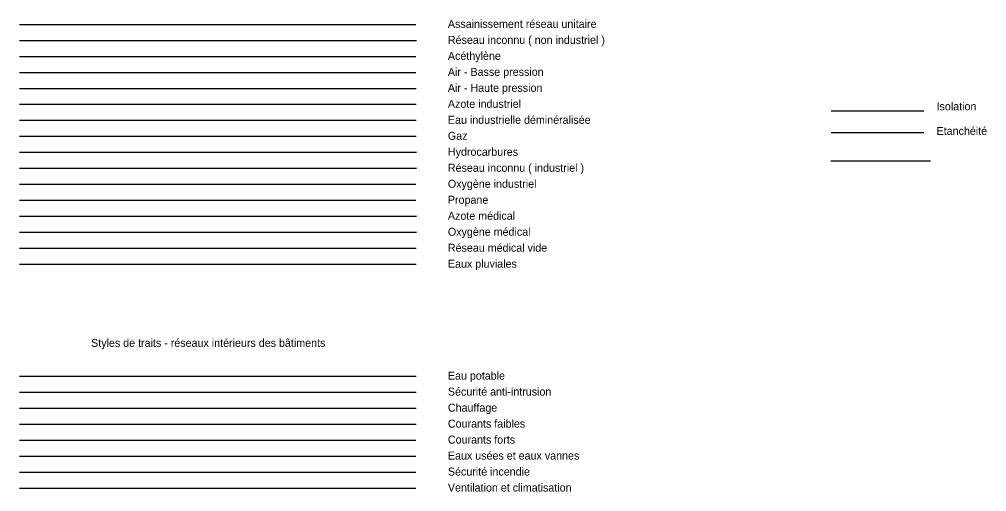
# Model space of a CAD drawing. Extents: x 3494.1 to 3554.6, y -18944.5 to -18883.7.
# Drawn here: x 3494.1 to 3554.6, y -18944.5 to -18915 of the extents above; entities that cross this region are included whole.
import ezdxf

# ---------------------------------------------------------------- set-up
doc = ezdxf.new("R2010")
doc.units = 0
for name, color, linetype in [('GO_COUVERTURE', 7, 'Continuous'), ('R_ES_UNITAIRE_CANALISATION_CL_C', 7, 'Continuous'), ('R_INCONNU_CANALISATION_CL_C', 7, 'Continuous'), ('R_IND_ACETYLENE_CANALISATION_CL_C', 7, 'Continuous'), ('R_IND_AIR_BP_CANALISATION_CL_C', 7, 'Continuous'), ('R_IND_AIR_HP_CANALISATION_CL_C', 7, 'Continuous'), ('R_IND_AZOTE_CANALISATION_CL_C', 7, 'Continuous'), ('R_IND_EAU_DEMINERALISEE_CANALISATION_CL_C', 7, 'Continuous'), ('R_IND_GAZ_NAT_CANALISATION_CL_C', 7, 'Continuous'), ('R_IND_HYDROCARBURE_CANALISATION_CL_C', 7, 'Continuous'), ('R_IND_INDUS_INCON_CANALISATION_CL_C', 7, 'Continuous'), ('R_IND_OXYGENE_CANALISATION_CL_C', 7, 'Continuous'), ('R_IND_PROPANE_CANALISATION_CL_C', 7, 'Continuous'), ('R_MED_AZOTE_CANALISATION_CL_C', 7, 'Continuous'), ('R_MED_OXYGENE_CANALISATION_CL_C', 7, 'Continuous'), ('R_MED_VIDE_CANALISATION_CL_C', 7, 'Continuous'), ('R_PLU_CANALISATION_CL_C', 7, 'Continuous'), ('SO_AEP_LIAISON', 7, 'Continuous'), ('SO_ANTI_INTRUSION_LIAISON', 7, 'Continuous'), ('SO_CHAUFFAGE_LIAISON', 7, 'Continuous'), ('SO_ELEC_C_FAIBLES_LIAISON', 7, 'Continuous'), ('SO_ELEC_C_FORTS_LIAISON', 7, 'Continuous'), ('SO_EU_EV_LIAISON', 7, 'Continuous'), ('SO_ISOLATION', 7, 'Continuous'), ('SO_SECU_INCENDIE_LIAISON', 7, 'Continuous'), ('SO_VMC_CVC_CTA_RES-TEXTE', 7, 'Continuous'), ('VOIRIE_VOIES FERREES', 7, 'Continuous')]:
    doc.layers.add(name, color=color, linetype=linetype)

msp = doc.modelspace()

# ---------------------------------------------------------------- linework, layer by layer
at = {"layer": 'GO_COUVERTURE'}
msp.add_line((3544.844, -18922.069), (3550.637, -18922.069), dxfattribs=at)
at = {"layer": 'R_ES_UNITAIRE_CANALISATION_CL_C'}
msp.add_line((3494.112, -18915.308), (3518.897, -18915.308), dxfattribs=at)
at = {"layer": 'R_INCONNU_CANALISATION_CL_C'}
msp.add_line((3494.112, -18916.308), (3518.927, -18916.308), dxfattribs=at)
at = {"layer": 'R_IND_ACETYLENE_CANALISATION_CL_C'}
msp.add_line((3494.112, -18917.308), (3518.883, -18917.308), dxfattribs=at)
at = {"layer": 'R_IND_AIR_BP_CANALISATION_CL_C'}
msp.add_line((3494.112, -18918.308), (3518.897, -18918.308), dxfattribs=at)
at = {"layer": 'R_IND_AIR_HP_CANALISATION_CL_C'}
msp.add_line((3494.112, -18919.308), (3518.912, -18919.308), dxfattribs=at)
at = {"layer": 'R_IND_AZOTE_CANALISATION_CL_C'}
msp.add_line((3494.112, -18920.308), (3518.912, -18920.308), dxfattribs=at)
at = {"layer": 'R_IND_EAU_DEMINERALISEE_CANALISATION_CL_C'}
msp.add_line((3494.112, -18921.308), (3518.912, -18921.308), dxfattribs=at)
at = {"layer": 'R_IND_GAZ_NAT_CANALISATION_CL_C'}
msp.add_line((3494.112, -18922.308), (3518.912, -18922.308), dxfattribs=at)
at = {"layer": 'R_IND_HYDROCARBURE_CANALISATION_CL_C'}
msp.add_line((3494.112, -18923.308), (3518.927, -18923.308), dxfattribs=at)
at = {"layer": 'R_IND_INDUS_INCON_CANALISATION_CL_C'}
msp.add_line((3494.112, -18924.308), (3518.927, -18924.308), dxfattribs=at)
at = {"layer": 'R_IND_OXYGENE_CANALISATION_CL_C'}
msp.add_line((3494.112, -18925.308), (3518.897, -18925.308), dxfattribs=at)
at = {"layer": 'R_IND_PROPANE_CANALISATION_CL_C'}
msp.add_line((3494.112, -18926.308), (3518.897, -18926.308), dxfattribs=at)
at = {"layer": 'R_MED_AZOTE_CANALISATION_CL_C'}
msp.add_line((3494.112, -18927.308), (3518.927, -18927.308), dxfattribs=at)
at = {"layer": 'R_MED_OXYGENE_CANALISATION_CL_C'}
msp.add_line((3494.112, -18928.308), (3518.927, -18928.308), dxfattribs=at)
at = {"layer": 'R_MED_VIDE_CANALISATION_CL_C'}
msp.add_line((3494.112, -18929.308), (3518.912, -18929.308), dxfattribs=at)
at = {"layer": 'R_PLU_CANALISATION_CL_C'}
msp.add_line((3494.112, -18930.308), (3518.912, -18930.308), dxfattribs=at)
at = {"layer": 'SO_AEP_LIAISON'}
msp.add_line((3494.112, -18937.308), (3518.912, -18937.308), dxfattribs=at)
at = {"layer": 'SO_ANTI_INTRUSION_LIAISON'}
msp.add_line((3494.112, -18938.308), (3518.912, -18938.308), dxfattribs=at)
at = {"layer": 'SO_CHAUFFAGE_LIAISON'}
msp.add_line((3494.112, -18939.308), (3518.912, -18939.308), dxfattribs=at)
at = {"layer": 'SO_ELEC_C_FAIBLES_LIAISON'}
msp.add_line((3494.112, -18940.308), (3518.912, -18940.308), dxfattribs=at)
at = {"layer": 'SO_ELEC_C_FORTS_LIAISON'}
msp.add_line((3494.112, -18941.308), (3518.897, -18941.308), dxfattribs=at)
at = {"layer": 'SO_EU_EV_LIAISON'}
msp.add_line((3494.112, -18942.308), (3518.897, -18942.308), dxfattribs=at)
at = {"layer": 'SO_ISOLATION'}
msp.add_line((3544.844, -18920.705), (3550.637, -18920.705), dxfattribs=at)
at = {"layer": 'SO_SECU_INCENDIE_LIAISON'}
msp.add_line((3494.112, -18943.308), (3518.883, -18943.308), dxfattribs=at)
at = {"layer": 'SO_VMC_CVC_CTA_RES-TEXTE'}
msp.add_line((3494.112, -18944.308), (3518.883, -18944.308), dxfattribs=at)
at = {"layer": 'VOIRIE_VOIES FERREES'}
msp.add_line((3544.823, -18923.85), (3551.054, -18923.85), dxfattribs=at)

# ---------------------------------------------------------------- texts
at = {"layer": 'GO_COUVERTURE'}
msp.add_text('Etanchéité', height=0.5, dxfattribs=at).set_placement((3551.437, -18922.223))
at = {"layer": 'R_ES_UNITAIRE_CANALISATION_CL_C'}
msp.add_text('Assainissement réseau unitaire', height=0.5, dxfattribs=at).set_placement((3520.895, -18915.527))
at = {"layer": 'R_INCONNU_CANALISATION_CL_C'}
msp.add_text('Réseau inconnu ( non industriel )', height=0.5, dxfattribs=at).set_placement((3520.895, -18916.527))
at = {"layer": 'R_IND_ACETYLENE_CANALISATION_CL_C'}
msp.add_text('Acéthylène', height=0.5, dxfattribs=at).set_placement((3520.895, -18917.527))
at = {"layer": 'R_IND_AIR_BP_CANALISATION_CL_C'}
msp.add_text('Air - Basse pression', height=0.5, dxfattribs=at).set_placement((3520.895, -18918.527))
at = {"layer": 'R_IND_AIR_HP_CANALISATION_CL_C'}
msp.add_text('Air - Haute pression', height=0.5, dxfattribs=at).set_placement((3520.895, -18919.527))
at = {"layer": 'R_IND_AZOTE_CANALISATION_CL_C'}
msp.add_text('Azote industriel', height=0.5, dxfattribs=at).set_placement((3520.895, -18920.527))
at = {"layer": 'R_IND_EAU_DEMINERALISEE_CANALISATION_CL_C'}
msp.add_text('Eau industrielle déminéralisée', height=0.5, dxfattribs=at).set_placement((3520.895, -18921.527))
at = {"layer": 'R_IND_GAZ_NAT_CANALISATION_CL_C'}
msp.add_text('Gaz', height=0.5, dxfattribs=at).set_placement((3520.895, -18922.527))
at = {"layer": 'R_IND_HYDROCARBURE_CANALISATION_CL_C'}
msp.add_text('Hydrocarbures', height=0.5, dxfattribs=at).set_placement((3520.895, -18923.527))
at = {"layer": 'R_IND_INDUS_INCON_CANALISATION_CL_C'}
msp.add_text('Réseau inconnu ( industriel )', height=0.5, dxfattribs=at).set_placement((3520.895, -18924.527))
at = {"layer": 'R_IND_OXYGENE_CANALISATION_CL_C'}
msp.add_text('Oxygène industriel', height=0.5, dxfattribs=at).set_placement((3520.895, -18925.527))
at = {"layer": 'R_IND_PROPANE_CANALISATION_CL_C'}
msp.add_text('Propane', height=0.5, dxfattribs=at).set_placement((3520.895, -18926.527))
at = {"layer": 'R_MED_AZOTE_CANALISATION_CL_C'}
msp.add_text('Azote médical', height=0.5, dxfattribs=at).set_placement((3520.895, -18927.527))
at = {"layer": 'R_MED_OXYGENE_CANALISATION_CL_C'}
msp.add_text('Oxygène médical', height=0.5, dxfattribs=at).set_placement((3520.895, -18928.527))
at = {"layer": 'R_MED_VIDE_CANALISATION_CL_C'}
msp.add_text('Réseau médical vide', height=0.5, dxfattribs=at).set_placement((3520.895, -18929.527))
at = {"layer": 'R_PLU_CANALISATION_CL_C'}
msp.add_text('Eaux pluviales', height=0.5, dxfattribs=at).set_placement((3520.895, -18930.527))
at = {"layer": 'SO_AEP_LIAISON'}
msp.add_text('Eau potable', height=0.5, dxfattribs=at).set_placement((3520.895, -18937.527))
at = {"layer": 'SO_ANTI_INTRUSION_LIAISON'}
msp.add_text('Sécurité anti-intrusion', height=0.5, dxfattribs=at).set_placement((3520.895, -18938.527))
at = {"layer": 'SO_CHAUFFAGE_LIAISON'}
msp.add_text('Chauffage', height=0.5, dxfattribs=at).set_placement((3520.895, -18939.527))
at = {"layer": 'SO_ELEC_C_FAIBLES_LIAISON'}
msp.add_text('Courants faibles', height=0.5, dxfattribs=at).set_placement((3520.895, -18940.527))
at = {"layer": 'SO_ELEC_C_FORTS_LIAISON'}
msp.add_text('Courants forts', height=0.5, dxfattribs=at).set_placement((3520.895, -18941.527))
at = {"layer": 'SO_EU_EV_LIAISON'}
msp.add_text('Eaux usées et eaux vannes', height=0.5, dxfattribs=at).set_placement((3520.895, -18942.527))
at = {"layer": 'SO_ISOLATION'}
msp.add_text('Isolation', height=0.5, dxfattribs=at).set_placement((3551.437, -18920.682))
at = {"layer": 'SO_SECU_INCENDIE_LIAISON'}
msp.add_text('Sécurité incendie', height=0.5, dxfattribs=at).set_placement((3520.895, -18943.527))
at = {"layer": 'SO_VMC_CVC_CTA_RES-TEXTE'}
for s, p in [('Styles de traits - réseaux intérieurs des bâtiments', (3498.597, -18935.478)), ('Ventilation et climatisation', (3520.895, -18944.527))]:
    msp.add_text(s, height=0.5, dxfattribs=at).set_placement(p)

doc.saveas('drawing.dxf')
